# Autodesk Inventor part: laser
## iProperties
Shininess: 64.0
Length Units: 11269
Angle Units: 11279
Time Units: 11290
Mass Units: 11283
Length Display Precision: 3
Angle Display Precision: 2
Compacted: True
Part Number: laser
Document SubType Name: Modeling
Created: 2004-07
Designer: Peter
Manufacturer: Standard
Standards Organization: Custom
Density: 0.0
Volumn: 0.0
Area: 0.0
PropertySet Name: Model Information
Control State: 0
Master: False
Checked Out: False
Author: Peter
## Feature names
1. Extrusion1
2. Hole1
3. Hole2
